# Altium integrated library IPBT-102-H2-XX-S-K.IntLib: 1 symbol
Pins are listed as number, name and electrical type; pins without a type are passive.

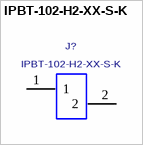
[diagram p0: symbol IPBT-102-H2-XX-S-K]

## IPBT-102-H2-XX-S-K
designator J?
.165 SINGLE ROW TERMINAL ASSEMBLY.; MANUFACTURER: SAMTEC
footprint IPBT-102-H2-XX-S-K
pins: 1, 2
